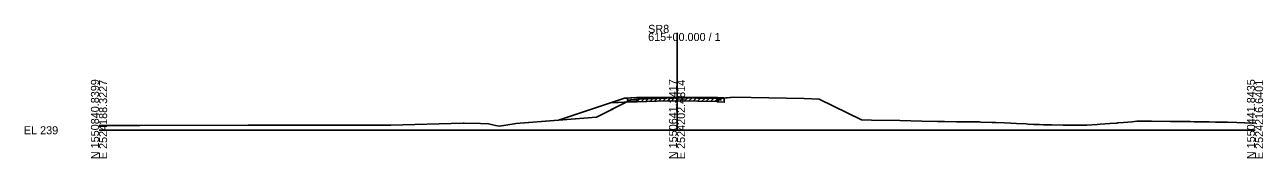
# Model space of a CAD drawing. Extents: x -26 to 2803, y -10 to 19537.
# Drawn here: x -25.7 to 402.8, y 19490.3 to 19536.6 of the extents above; entities that cross this region are included whole.
import ezdxf

# ---------------------------------------------------------------- set-up
doc = ezdxf.new("R2010")
doc.units = 0
for name, color, linetype in [('1', 7, 'Continuous'), ('Draft_XS_Grid', 7, 'Continuous'), ('Draft_XS_Text', 7, 'Continuous'), ('DTM_P_SUBGRADE_1', 7, 'Continuous'), ('DTM_X_GROUND', 7, 'Continuous'), ('SLOPE_STAKES_FILL', 7, 'Continuous'), ('XS_P_ASPHALT', 7, 'Continuous'), ('XS_P_SHOULDER', 7, 'Continuous')]:
    doc.layers.add(name, color=color, linetype=linetype)

msp = doc.modelspace()

# ---------------------------------------------------------------- linework, layer by layer
at = {"layer": '1'}
for p, q in [((200, 19500), (200, 19533.73)), ((0, 19500), (200, 19500)), ((200, 19500), (400, 19500))]:
    msp.add_line(p, q, dxfattribs=at)
at = {"layer": 'Draft_XS_Grid'}
for p, q in [((195.1, 19510.1), (196.13, 19511.13)), ((196.6, 19510.14), (197.63, 19511.17)), ((198.1, 19510.19), (199.13, 19511.22)), ((199.6, 19510.23), (200.61, 19511.23)), ((201.1, 19510.22), (202.09, 19511.2)), ((202.6, 19510.19), (203.59, 19511.18)), ((204.1, 19510.17), (205.09, 19511.15)), ((205.6, 19510.14), (206.59, 19511.12)), ((207.1, 19510.11), (208.09, 19511.09)), ((186.1, 19509.84), (187.13, 19510.87)), ((186.1, 19509.84), (186.1, 19510.84)), ((186.1, 19509.84), (193, 19510.04)), ((187.6, 19509.89), (188.63, 19510.92)), ((189.1, 19509.93), (190.13, 19510.96)), ((190.6, 19509.97), (191.63, 19511)), ((192.1, 19510.02), (193.13, 19511.04)), ((193, 19510.04), (200.1, 19510.24)), ((193.6, 19510.06), (194.63, 19511.09)), ((200.1, 19510.24), (214.2, 19509.97)), ((208.6, 19510.08), (209.59, 19511.06)), ((210.1, 19510.05), (211.09, 19511.03)), ((211.6, 19510.02), (212.59, 19511)), ((213.1, 19509.99), (214.09, 19510.97)), ((214.2, 19510.97), (214.2, 19509.97))]:
    msp.add_line(p, q, dxfattribs=at)
at = {"layer": 'Draft_XS_Text'}
for p, q in [((214.2, 19510.97), (219.5, 19511.44)), ((219.5, 19511.44), (231.77, 19511.2)), ((231.77, 19511.2), (244.04, 19510.97)), ((244.04, 19510.97), (249.16, 19510.77)), ((249.16, 19510.77), (263.84, 19503.59))]:
    msp.add_line(p, q, dxfattribs=at)
for points in [[(0, 19501.66), (14.1, 19501.69), (51.57, 19501.75), (77.44, 19501.77), (101.02, 19501.78), (126.01, 19502.51), (126.32, 19502.52), (131.98, 19502.31), (134.71, 19502.22), (137.16, 19501.71), (138.58, 19501.42), (143.62, 19502.24), (144.22, 19502.34), (145.7, 19502.46), (172.12, 19504.59), (184.06, 19510.55), (186.1, 19510.84), (193, 19511.04), (200.1, 19511.24), (214.2, 19510.97)], [(263.84, 19503.59), (267.27, 19503.54), (277.15, 19503.36), (284.67, 19503.13), (290.11, 19503.08), (292.6, 19503.02), (296.76, 19502.97), (300.01, 19502.97), (301.89, 19502.97), (304.64, 19502.89), (305.1, 19502.87), (309.05, 19502.75), (310.32, 19502.68), (313.34, 19502.58), (315.55, 19502.46), (317.5, 19502.38), (320.8, 19502.18), (321.51, 19502.15), (323.44, 19502.02), (325.46, 19501.96), (326.84, 19501.92), (329.53, 19501.84), (333.64, 19501.72), (337.37, 19501.78), (340.42, 19501.82), (341.05, 19501.83), (341.77, 19501.83), (345.33, 19502.06), (346.41, 19502.13), (349.77, 19502.35), (352.18, 19502.51), (352.58, 19502.54), (354.47, 19502.68), (357.47, 19502.98), (359.05, 19503.14), (363.92, 19503.11), (364.22, 19503.11), (370.78, 19503.07), (371.59, 19503.05), (377.53, 19503), (378.96, 19502.96), (384.11, 19502.92), (386.33, 19502.85), (390.46, 19502.8), (393.7, 19502.67), (396.44, 19502.64), (400, 19502.45)]]:
    msp.add_lwpolyline(points, dxfattribs=at)
at = {"layer": 'DTM_P_SUBGRADE_1'}
for p, q in [((216.37, 19511.16), (216.37, 19509.71)), ((184, 19509.81), (176.98, 19509.53)), ((186.1, 19509.81), (184, 19509.81)), ((186.1, 19510.56), (186.1, 19509.81)), ((214, 19510.56), (214, 19509.81)), ((214, 19509.81), (216.37, 19509.71))]:
    msp.add_line(p, q, dxfattribs=at)
at = {"layer": 'DTM_X_GROUND'}
for p, q in [((181.83, 19511.14), (159, 19503.53)), ((186, 19511.31), (181.83, 19511.14)), ((200, 19511.31), (186, 19511.31)), ((200, 19511.31), (214, 19511.31)), ((214, 19511.31), (216.2, 19511.22)), ((216.2, 19511.22), (216.37, 19511.16))]:
    msp.add_line(p, q, dxfattribs=at)
at = {"layer": 'SLOPE_STAKES_FILL'}
for p, q in [((159, 19503.53), (181.83, 19511.14)), ((181.83, 19511.14), (186, 19511.31)), ((186, 19511.31), (200, 19511.31)), ((200, 19511.31), (214, 19511.31)), ((214, 19511.31), (216.2, 19511.22)), ((216.2, 19511.22), (216.37, 19511.16)), ((216.37, 19511.16), (219.5, 19511.44)), ((219.5, 19511.44), (231.77, 19511.2)), ((231.77, 19511.2), (244.04, 19510.97)), ((244.04, 19510.97), (249.16, 19510.77)), ((249.16, 19510.77), (263.84, 19503.59))]:
    msp.add_line(p, q, dxfattribs=at)
for points in [[(0, 19501.66), (14.1, 19501.69), (51.57, 19501.75), (77.44, 19501.77), (101.02, 19501.78), (126.01, 19502.51), (126.32, 19502.52), (131.98, 19502.31), (134.71, 19502.22), (137.16, 19501.71), (138.58, 19501.42), (143.62, 19502.24), (144.22, 19502.34), (145.7, 19502.46), (159, 19503.53)], [(263.84, 19503.59), (267.27, 19503.54), (277.15, 19503.36), (284.67, 19503.13), (290.11, 19503.08), (292.6, 19503.02), (296.76, 19502.97), (300.01, 19502.97), (301.89, 19502.97), (304.64, 19502.89), (305.1, 19502.87), (309.05, 19502.75), (310.32, 19502.68), (313.34, 19502.58), (315.55, 19502.46), (317.5, 19502.38), (320.8, 19502.18), (321.51, 19502.15), (323.44, 19502.02), (325.46, 19501.96), (326.84, 19501.92), (329.53, 19501.84), (333.64, 19501.72), (337.37, 19501.78), (340.42, 19501.82), (341.05, 19501.83), (341.77, 19501.83), (345.33, 19502.06), (346.41, 19502.13), (349.77, 19502.35), (352.18, 19502.51), (352.58, 19502.54), (354.47, 19502.68), (357.47, 19502.98), (359.05, 19503.14), (363.92, 19503.11), (364.22, 19503.11), (370.78, 19503.07), (371.59, 19503.05), (377.53, 19503), (378.96, 19502.96), (384.11, 19502.92), (386.33, 19502.85), (390.46, 19502.8), (393.7, 19502.67), (396.44, 19502.64), (400, 19502.45)]]:
    msp.add_lwpolyline(points, dxfattribs=at)
at = {"layer": 'XS_P_ASPHALT'}
for p, q in [((182.85, 19510.43), (182.85, 19511.18)), ((214, 19510.56), (214, 19511.31)), ((215.17, 19510.51), (215.17, 19511.26)), ((186.1, 19510.56), (182.85, 19510.43)), ((214, 19510.56), (215.17, 19510.51))]:
    msp.add_line(p, q, dxfattribs=at)
at = {"layer": 'XS_P_SHOULDER'}
for points in [[(182.85, 19510.43), (182.85, 19511.18), (181.83, 19511.14), (176.98, 19509.53), (182.44, 19509.75), (183.9, 19510.48)], [(200, 19511.31), (214, 19511.31), (214, 19510.98), (200.1, 19511.24), (193, 19511.04), (186.1, 19510.84), (184.06, 19510.55), (183.9, 19510.48), (182.85, 19510.43), (182.85, 19511.18), (186, 19511.31)], [(214, 19510.98), (214, 19511.31), (215.17, 19511.26), (215.17, 19511.06), (214.2, 19510.97)], [(214.2, 19510.55), (215.17, 19510.51), (215.17, 19511.06), (216.37, 19511.16), (216.37, 19509.71), (214, 19509.81), (214, 19509.98), (214.2, 19509.97)], [(215.17, 19511.06), (216.37, 19511.16), (216.2, 19511.22), (215.17, 19511.26)], [(182.44, 19509.75), (176.98, 19509.53), (159, 19503.53), (172.12, 19504.59)], [(184, 19509.81), (182.44, 19509.75), (183.9, 19510.48), (186.1, 19510.56), (186.1, 19509.84), (186.1, 19509.81)], [(186.1, 19510.56), (186.1, 19510.84), (184.06, 19510.55), (183.9, 19510.48)], [(214, 19510.56), (214.2, 19510.55), (214.2, 19510.97), (214, 19510.98)], [(214, 19509.98), (214.2, 19509.97), (214.2, 19510.55), (214, 19510.56)], [(214.2, 19510.55), (215.17, 19510.51), (215.17, 19511.06), (214.2, 19510.97)]]:
    msp.add_lwpolyline(points, close=True, dxfattribs=at)

# ---------------------------------------------------------------- texts
at = {"layer": '1'}
for s, p in [('SR8', (190, 19533.73)), ('615+00.000 / 1', (190, 19530.93)), ('EL 239', (-26, 19498.6))]:
    msp.add_text(s, height=2.8, dxfattribs=at).set_placement(p)
for s, p in [('N 1550840.8399', (0, 19490)), ('E 2524188.3227', (2.8, 19490)), ('N 1550641.3417', (200, 19490)), ('E 2524202.4814', (202.8, 19490)), ('N 1550441.8435', (400, 19490)), ('E 2524216.6401', (402.8, 19490))]:
    msp.add_text(s, height=2.8, rotation=90, dxfattribs=at).set_placement(p)

doc.saveas('drawing.dxf')
